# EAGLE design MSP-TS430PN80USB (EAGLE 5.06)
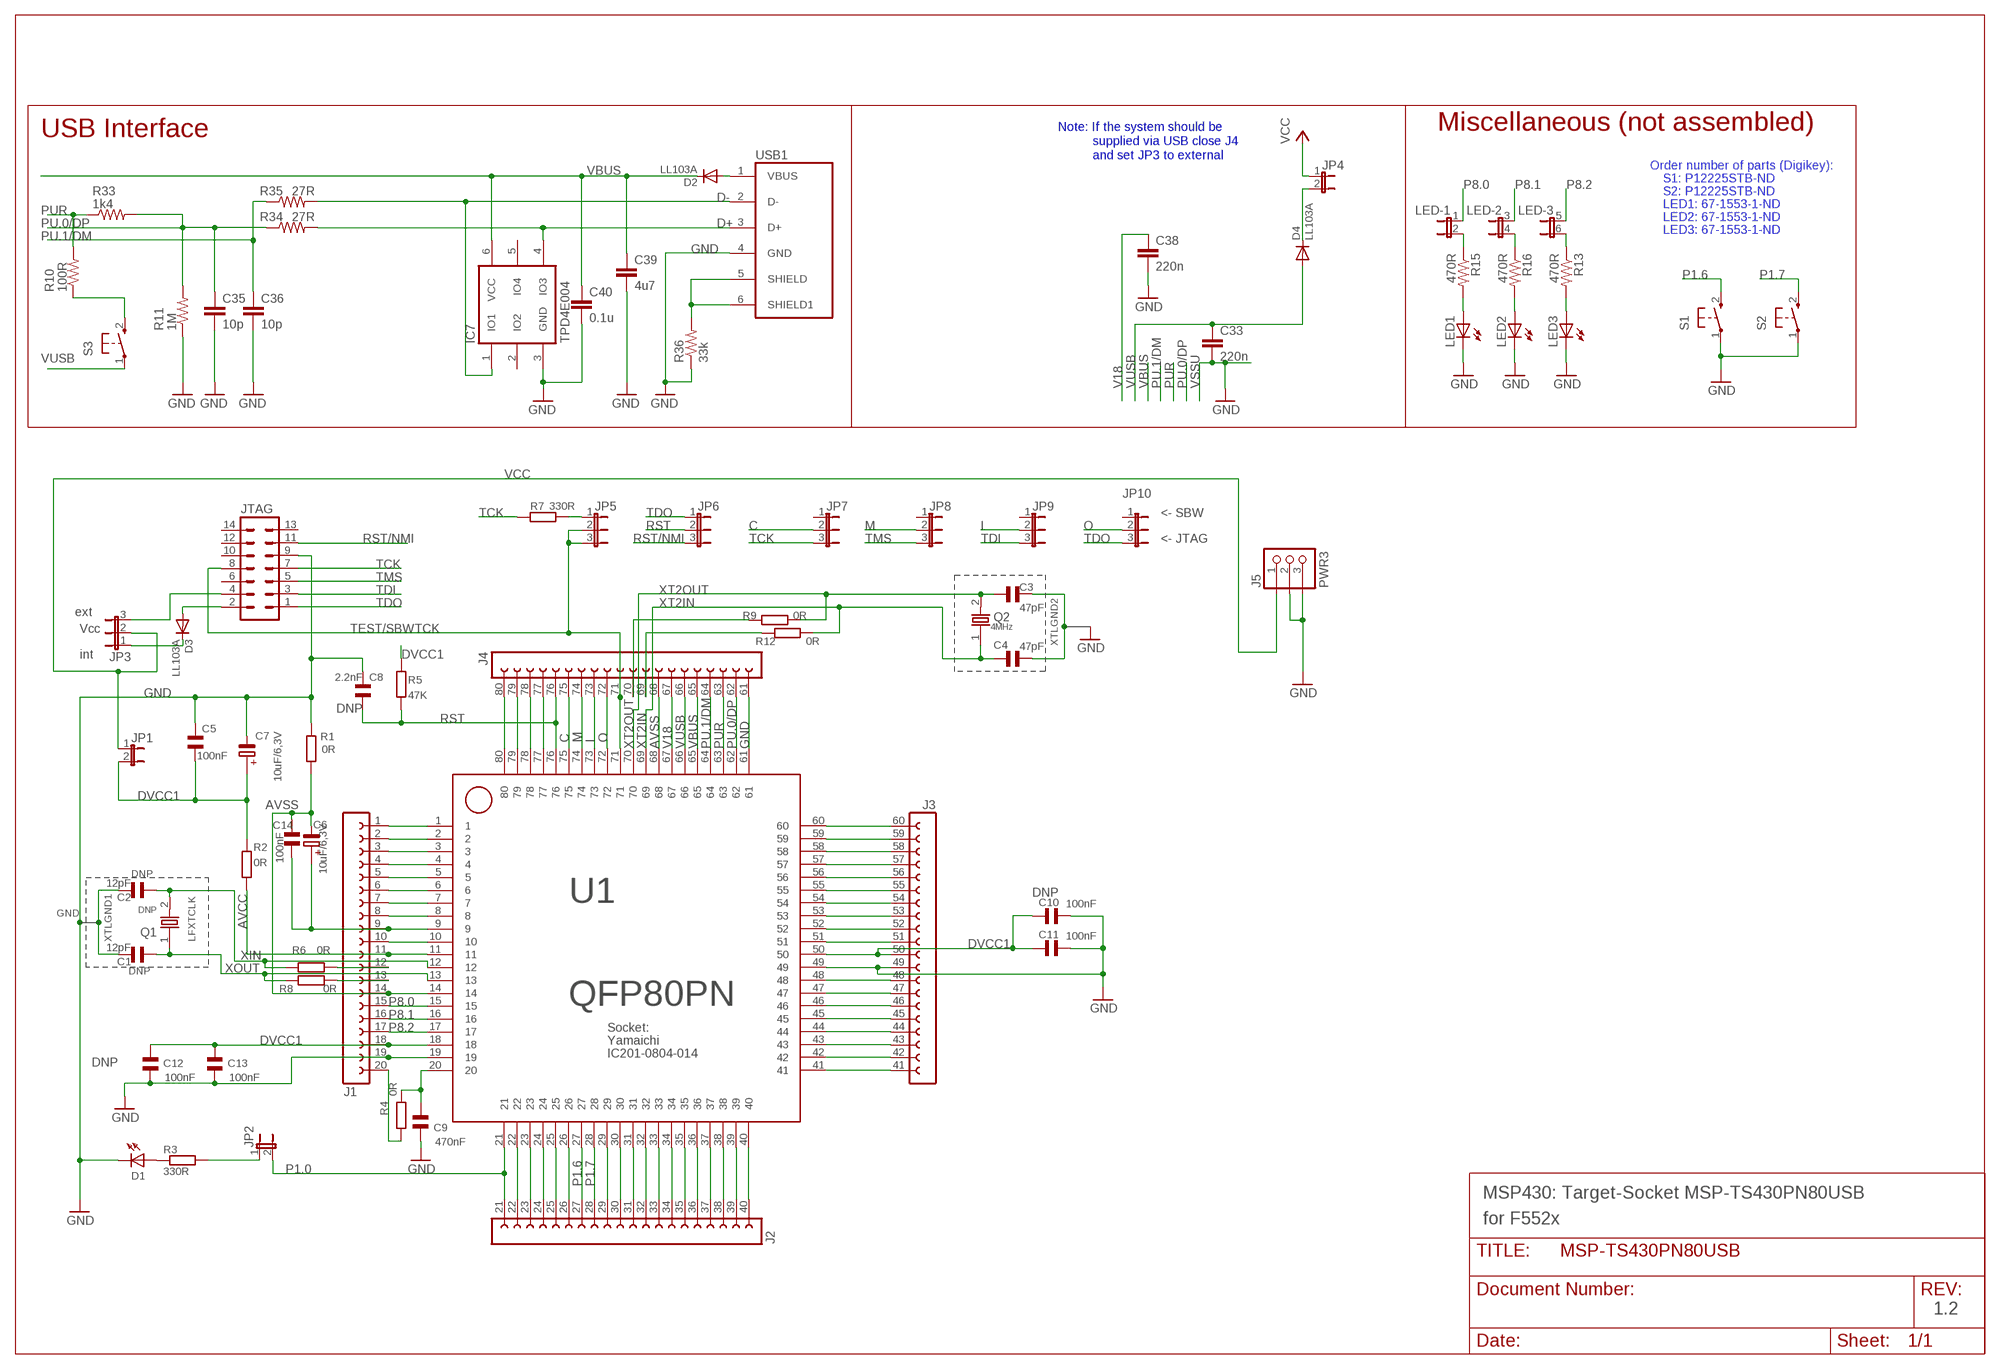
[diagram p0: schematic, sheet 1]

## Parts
C1  12pF  CSMD0805  [CSMD0805]
C2  12pF  CSMD0805  [CSMD0805]
C3  47pF  CSMD0805  [CSMD0805]
C4  47pF  CSMD0805  [CSMD0805]
C5  100nF  CSMD0805  [CSMD0805]
C6  10uF/6,3V  ELKO_1210  [1210ELKO]
C7  10uF/6,3V  ELKO_1210  [1210ELKO]
C8  2.2nF  CSMD0805  [CSMD0805]
C9  470nF  CSMD0805  [CSMD0805]
C10  100nF  CSMD0805  [CSMD0805]
C11  100nF  CSMD0805  [CSMD0805]
C12  100nF  CSMD0805  [CSMD0805]
C13  100nF  CSMD0805  [CSMD0805]
C14  100nF  CSMD0805  [CSMD0805]
C33  220n  C-EUC0603  [C0603]
C35  10p  C-EUC0603  [C0603]
C36  10p  C-EUC0603  [C0603]
C38  220n  C-EUC0603  [C0603]
C39  4u7  C-EUC0603  [C0603]
C40  0.1u  C-EUC0603  [C0603]
D1  LED30805  [DIODE_0805]
D2  LL103A  D  [SOD-80]
D3  LL103A  D  [SOD-80]
D4  LL103A  D  [SOD-80]
IC7  TPD4E004  [DRY6]
J1  FE20-1-1  [FE20-1-1]
J2  FE20-1-2  [FE20-1-2]
J3  FE20-1-3  [FE20-1-3]
J4  FE20-1-4  [FE20-1-4]
J5  PWR3  [PWR3]
JP1  JP1E  [JP1]
JP2  JP1E  [JP1]
JP3  JP2ESMALLPAD  [JP2Z]
JP4  JP1E  [JP1]
JP5  JP2ESMALLPAD  [JP2Z]
JP6  JP2ESMALLPAD  [JP2Z]
JP7  JP2ESMALLPAD  [JP2Z]
JP8  JP2ESMALLPAD  [JP2Z]
JP9  JP2ESMALLPAD  [JP2Z]
JP10  JP2ESMALLPAD  [JP2Z]
JTAG  ML14  [ML14]
LED  JP3QE  [JP3Q]
LED1  LEDCHIPLED_0603  [CHIPLED_0603]
LED2  LEDCHIPLED_0603  [CHIPLED_0603]
LED3  LEDCHIPLED_0603  [CHIPLED_0603]
Q1  HCTC_XTLTCV  [TCV]
Q2  HCTC_XTLTCV  [TCV]
R1  0R  R_0805  [0805]
R2  0R  R_0805  [0805]
R3  330R  R_0805  [0805]
R4  0R  R_0805  [0805]
R5  47K  R_0805  [0805]
R6  0R  R_0805  [0805]
R7  330R  R_0805  [0805]
R8  0R  R_0805  [0805]
R9  0R  R_0805  [0805]
R10  100R  R-US_R0603  [R0603]
R11  1M  R-US_R0603  [R0603]
R12  0R  R_0805  [0805]
R13  470R  R-US_R0603  [R0603]
R15  470R  R-US_R0603  [R0603]
R16  470R  R-US_R0603  [R0603]
R33  1k4  R-US_R0603  [R0603]
R34  27R  R-US_R0603  [R0603]
R35  27R  R-US_R0603  [R0603]
R36  33k  R-US_R0603  [R0603]
S1  PB  [PBTH]
S2  PB  [PBTH]
S3  PB  [PBTH]
U1  QFP80PN  [QFP80PN]
USB1  USB_RECEPTACLE  [USB_BUCHSE]

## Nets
AVCC: J1.11 R2.1 U1.11
AVSS: C6.- C14.2 J1.14 J4.68 R1.2 U1.14 U1.68
C: J4.75 JP7.2 U1.75
D+: IC7.4(IO3) R34.2 USB1.3(D+)
D-: IC7.1(IO1) R35.2 USB1.2(D-)
DVCC1: C5.1 C7.+ C10.1 C11.1 C12.2 C13.2 J1.18 J3.50 JP1.2 R2.2 R5.2 U1.18 U1.50
GND: C5.2 C7.- C8.1 C9.1 C10.2 C11.2 C12.1 C13.1 C33.2 C35.2 C36.2 C38.2 C39.2 C40.2 D1.K IC7.3(GND) J1.19 J3.49 J4.61 J5.2 J5.3 JTAG.9 LED1.C LED2.C LED3.C R1.1 R11.1 R36.1 S1.1(P) S2.1(P) U1.19 U1.49 U1.61 USB1.4(GND)
I: J4.73 JP9.2 U1.73
M: J4.74 JP8.2 U1.74
N$1: JP2.1 R3.2
N$2: D4.2(K) JP4.2
N$3: C6.+ C14.1 J1.9 U1.9
N$4: J1.20 R4.1
N$5: J4.70 R9.2
N$6: J1.12 R6.2
N$7: D3.2(K) JP3.1
N$8: R36.2 USB1.5(SHIELD) USB1.6(SHIELD1)
N$9: J1.1 U1.1
N$10: J1.13 R8.2
N$11: J4.69 R12.2
N$12: J1.2 U1.2
N$13: J1.3 U1.3
N$14: J2.30 U1.30
N$15: J1.4 U1.4
N$16: J2.39 U1.39
N$17: J4.80 U1.80
N$18: D1.A R3.1
N$19: J1.6 U1.6
N$20: J2.31 U1.31
N$21: J2.35 U1.35
N$22: J1.10 U1.10
N$23: JP3.3 JTAG.4
N$24: LED3.A R13.2
N$25: J3.47 U1.47
N$26: C9.2 R4.2 U1.20
N$27: J3.51 U1.51
N$28: J1.7 U1.7
N$29: J4.78 U1.78
N$30: LED.6 R13.1
N$31: R10.1 S3.2(S)
N$32: LED1.A R15.2
N$33: J3.48 U1.48
N$34: J2.32 U1.32
N$35: LED2.A R16.2
N$36: LED.2 R15.1
N$37: LED.4 R16.1
N$38: D3.1(A) JTAG.2
N$41: J2.22 U1.22
N$43: J2.23 U1.23
N$44: J2.24 U1.24
N$45: J2.25 U1.25
N$46: J2.26 U1.26
N$50: J2.29 U1.29
N$51: D2.1(A) USB1.1(VBUS)
N$54: J4.77 U1.77
N$55: J2.33 U1.33
N$56: J2.34 U1.34
N$57: JP5.1 R7.1
N$58: J2.36 U1.36
N$59: J2.37 U1.37
N$60: J2.38 U1.38
N$62: J2.40 U1.40
N$70: J3.41 U1.41
N$71: J3.42 U1.42
N$72: J3.43 U1.43
N$73: J3.44 U1.44
N$74: J3.45 U1.45
N$75: J3.46 U1.46
N$87: J3.52 U1.52
N$88: J3.53 U1.53
N$89: J3.54 U1.54
N$90: J3.55 U1.55
N$91: J3.56 U1.56
N$92: J3.57 U1.57
N$93: J3.58 U1.58
N$94: J3.59 U1.59
N$95: J3.60 U1.60
N$99: J1.8 U1.8
N$100: J4.79 U1.79
N$102: J1.5 U1.5
O: J4.72 JP10.2 U1.72
P1.0: J2.21 JP2.2 U1.21
P1.6: J2.27 S1.2(S) U1.27
P1.7: J2.28 S2.2(S) U1.28
P8.0: J1.15 LED.1 U1.15
P8.1: J1.16 LED.3 U1.16
P8.2: J1.17 LED.5 U1.17
PU.0/DP: C35.1 J4.62 R11.2 R33.2 R34.1 U1.62
PU.1/DM: C36.1 J4.64 R35.1 U1.64
PUR: J4.63 R10.2 R33.1 U1.63
RST: C8.2 J4.76 JP6.2 R5.1 U1.76
RST/NMI: JP6.3 JTAG.11
TCK: JP7.3 JTAG.7 R7.2
TDI: JP9.3 JTAG.3
TDO: JP6.1 JP10.3 JTAG.1
TEST/SBWTCK: J4.71 JP5.2 JP5.3 JTAG.8 U1.71
TMS: JP8.3 JTAG.5
V18: C38.1 J4.67 U1.67
VBUS: C39.1 C40.1 D2.2(K) IC7.6(VCC) J4.65 U1.65
VCC: J5.1 JP1.1 JP3.2 JP4.1
VUSB: C33.1 D4.1(A) J4.66 S3.1(P) U1.66
XIN: C2.1 Q1.2 R6.1 U1.12
XOUT: C1.1 Q1.1 R8.1 U1.13
XT2IN: C4.1 Q2.1 R12.1 U1.69
XT2OUT: C3.1 Q2.2 R9.1 U1.70
XTLGND1: C1.2 C2.2
XTLGND2: C3.2 C4.2
Unconnected: IC7.2(IO2) JP7.1 JP8.1 JP9.1 JP10.1 JTAG.6 JTAG.10 JTAG.12 JTAG.13 JTAG.14

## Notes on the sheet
- Note: If the system should be | Miscellaneous (not assembled)
- USB Interface
- supplied via USB close J4
- and set JP3 to external
- Order number of parts (Digikey):
- S1: P12225STB-ND
- S2: P12225STB-ND
- LED1: 67-1553-1-ND
- LED2: 67-1553-1-ND
- LED3: 67-1553-1-ND
- VSSU
- <- SBW
- <- JTAG
- ext
- 4MHz
- Vcc
- int
- DNP
- DNP
- DNP
- GND | DNP
- LFXTCLK
- DNP
- Socket:
- Yamaichi
- DNP | IC201-0804-014
- MSP430: Target-Socket MSP-TS430PN80USB
- for F552x
- 1.2

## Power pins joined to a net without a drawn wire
IO4: IC7.5(IO4)

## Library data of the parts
C1-C5 C8-C14 = cap:CSMD0805
C6 C7 = smd:ELKO_1210
C33 C35 C36 C38-C40 = rcl:C-EU: CAPACITOR, European symbol
D1 = MSP430:LED3
D2-D4 = smd:D
IC7 = gangprog:TPD4E004
J1 = CON-LSTA:FE20-1-1
J2 = CON-LSTA:FE20-1-2
J3 = CON-LSTA:FE20-1-3
J4 = CON-LSTA:FE20-1-4
J5 = MSP430:PWR3
JP1 JP2 JP4 = jumper:JP1E: JUMPER
JP3 JP5-JP10 = jumper:JP2E: JUMPER
JTAG = con-ml:ML14
LED = jumper:JP3QE: JUMPER
LED1-LED3 = led:LED: LED
Q1 Q2 = scrystal:HCTC_XTL
R1-R9 R12 = smd:R_0805
R10 R11 R33-R36 = rcl:R-US_: RESISTOR, American symbol
R13 R15 R16 = _MSP430:R-US_: RESISTOR, American symbol
S1-S3 = electricalmeter:PB: OMRON SWITCH
U1 = MSP430:QFP80PN
USB1 = susbfet:USB_RECEPTACLE: Lumberg: USB-Receptacle "B", 2413

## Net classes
0 default: width 0.254 mm

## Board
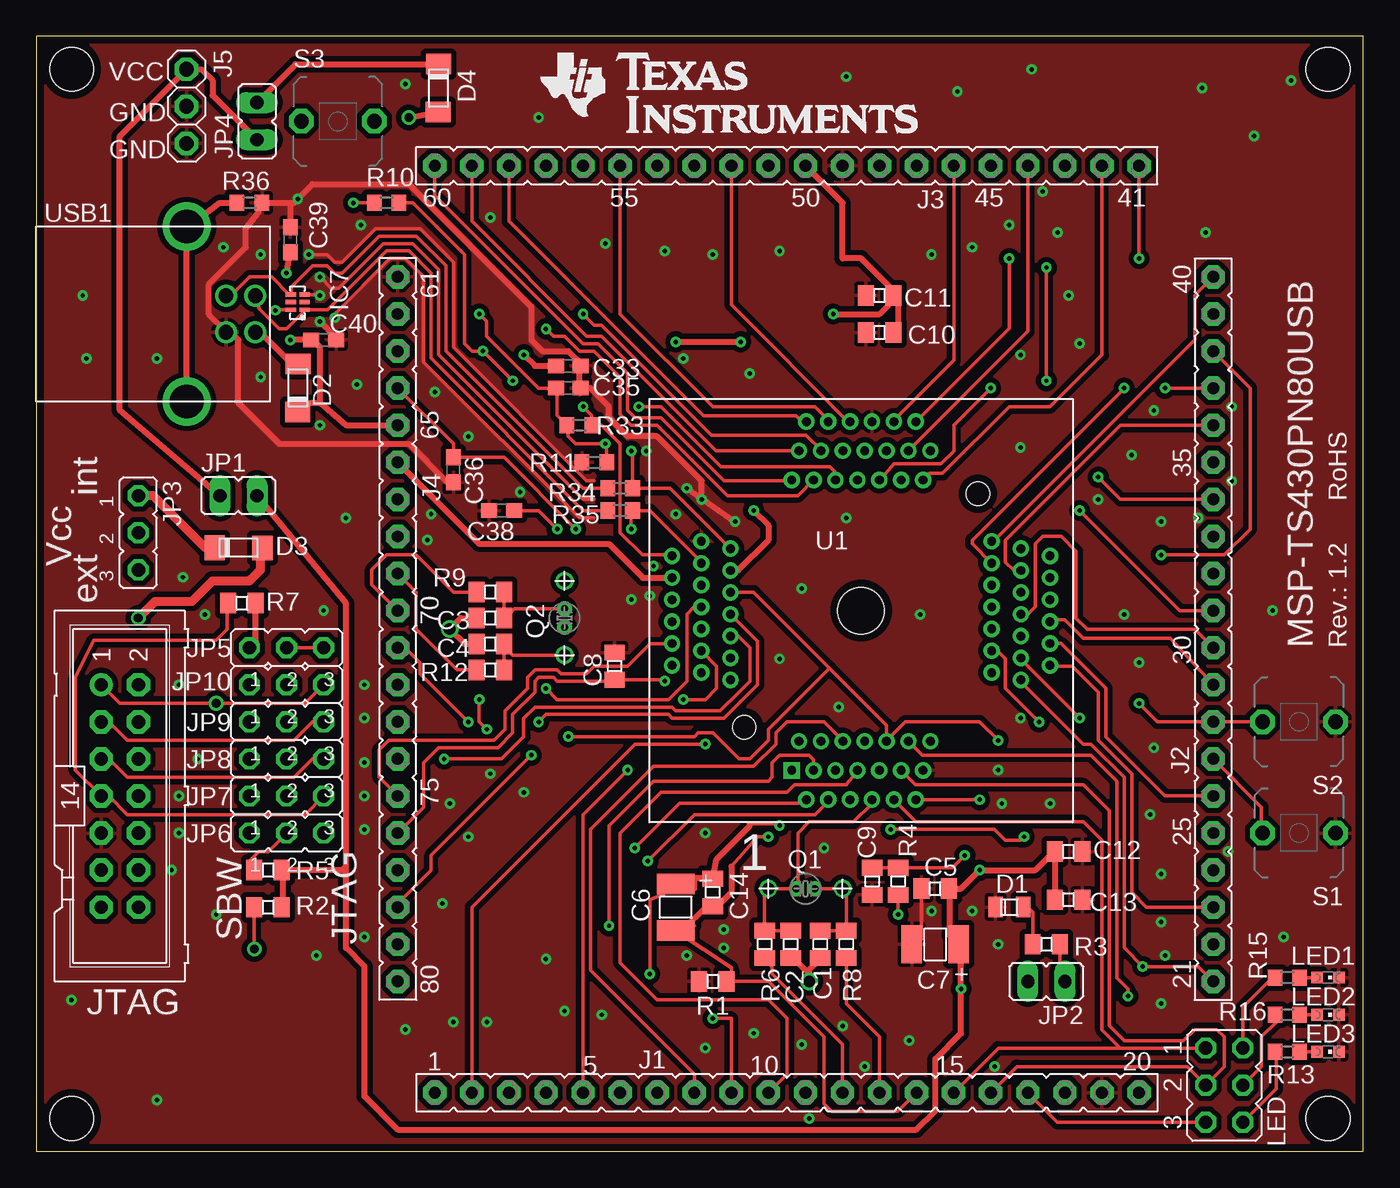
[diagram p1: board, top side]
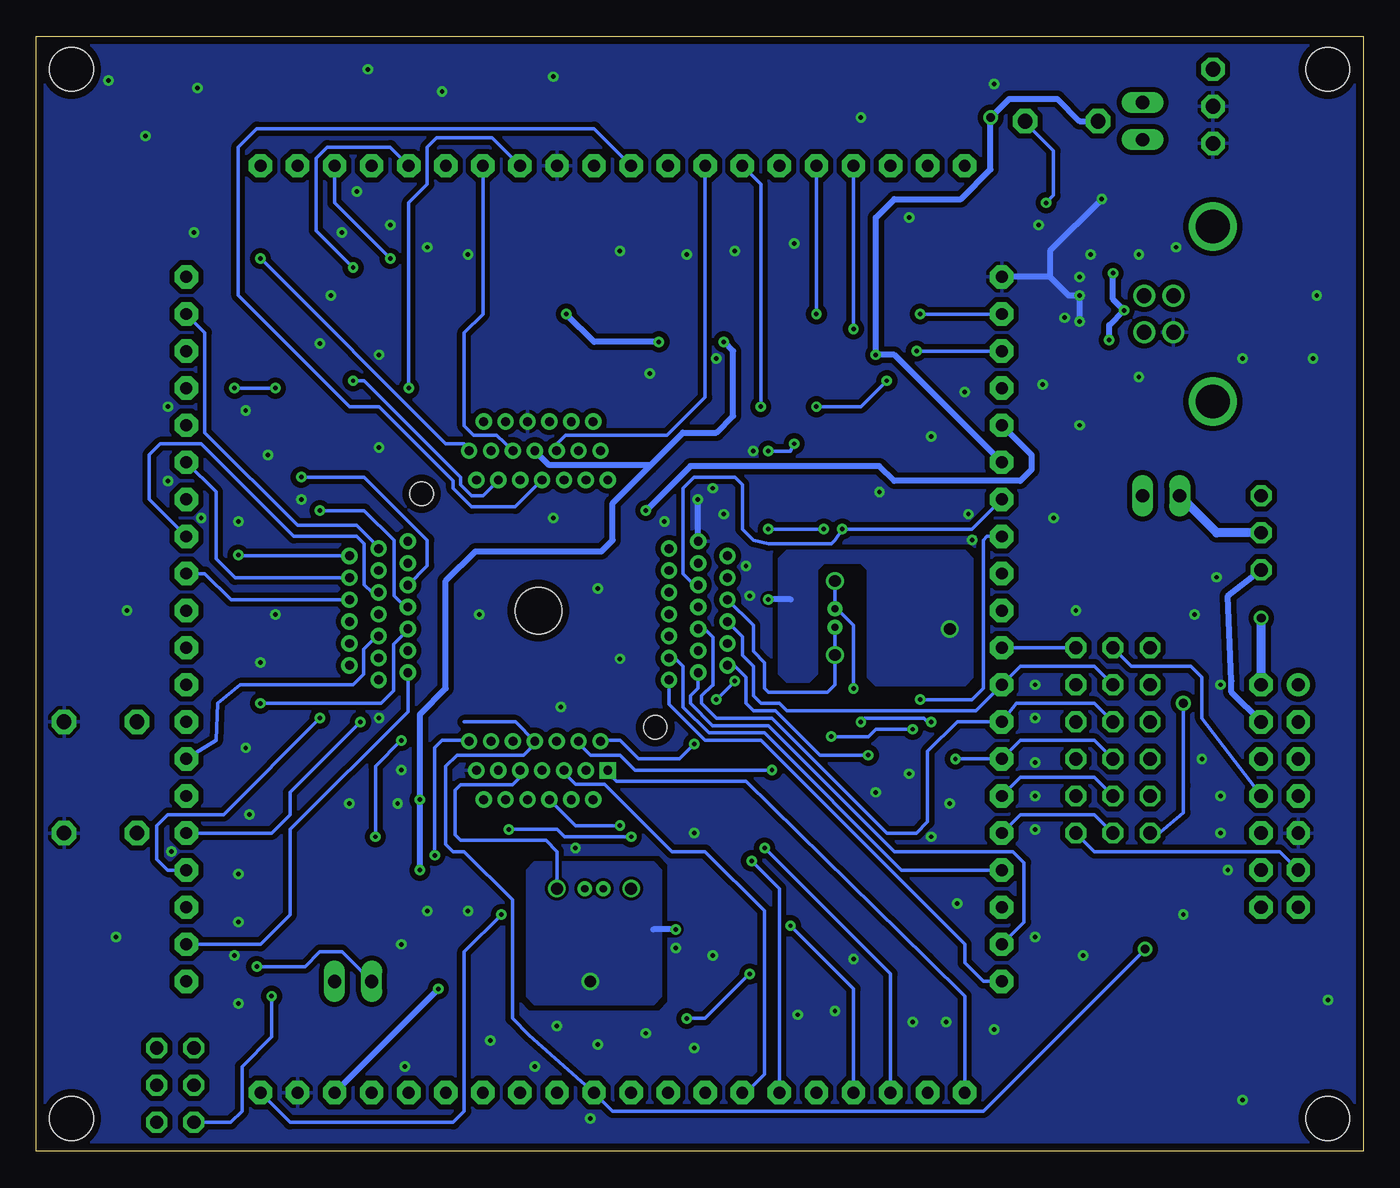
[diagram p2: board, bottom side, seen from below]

Size 90.91 x 76.38 mm. Coordinates in mm from the lower left corner, seen from the top.
Outline: 0,0 90.91,0 90.91,76.38 0,76.38 0,0
Copper layers (1*16): Top 0.035mm / dielectric 1.5mm / Bottom 0.035mm
Design rules "default *": minimum track width 8mil, minimum drill 12mil, track to track 8mil, track to pad 8mil, pad to pad 8mil, via to via 8mil, smd to smd 8mil, copper to edge 20mil, drill to drill 8mil, minimum pad ring 10mil, minimum via ring 8mil, stop-mask expansion 4mil, vias tented up to drill 0mil, thermal gap 10mil
Holes 3 mm at 2.41,74.13 88.51,74.13 88.51,2.25 2.41,2.25

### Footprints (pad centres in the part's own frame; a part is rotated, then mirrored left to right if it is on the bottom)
CSMD0805 = smd 1.092 x 1.397: 1 -0.94,0; 2 0.94,0
1210ELKO = smd 1.397 x 2.591: + 1.6,0; - -1.6,0
C0603 = smd 1.1 x 1: 1 -0.85,0; 2 0.85,0
DIODE_0805 = smd 1 x 1.4: A -0.94,0; K 0.94,0
SOD-80 = smd 1.397 x 1.702: 1 1.397,-0.025; 2 -1.88,0
DRY6 = smd 0.3 x 0.7: 1 -0.98,-2.254; 2 -0.457,-2.254; 3 0.066,-2.254; 4 0.066,-1.306; 5 -0.459,-1.306; 6 -0.98,-1.306
FE20-1-1 = drill 0.813 pad 1.6 octagon: 1 -24.13,0; 2 -21.59,0; 3 -19.05,0; 4 -16.51,0; 5 -13.97,0; 6 -11.43,0; 7 -8.89,0; 8 -6.35,0; 9 -3.81,0; 10 -1.27,0; 11 1.27,0; 12 3.81,0; 13 6.35,0; 14 8.89,0; 15 11.43,0; 16 13.97,0; 17 16.51,0; 18 19.05,0; 19 21.59,0; 20 24.13,0
FE20-1-2 = drill 0.813 pad 1.6 octagon: 21 -24.13,0; 22 -21.59,0; 23 -19.05,0; 24 -16.51,0; 25 -13.97,0; 26 -11.43,0; 27 -8.89,0; 28 -6.35,0; 29 -3.81,0; 30 -1.27,0; 31 1.27,0; 32 3.81,0; 33 6.35,0; 34 8.89,0; 35 11.43,0; 36 13.97,0; 37 16.51,0; 38 19.05,0; 39 21.59,0; 40 24.13,0
FE20-1-3 = drill 0.813 pad 1.6 octagon: 41 -24.13,0; 42 -21.59,0; 43 -19.05,0; 44 -16.51,0; 45 -13.97,0; 46 -11.43,0; 47 -8.89,0; 48 -6.35,0; 49 -3.81,0; 50 -1.27,0; 51 1.27,0; 52 3.81,0; 53 6.35,0; 54 8.89,0; 55 11.43,0; 56 13.97,0; 57 16.51,0; 58 19.05,0; 59 21.59,0; 60 24.13,0
FE20-1-4 = drill 0.813 pad 1.6 octagon: 61 -24.13,0; 62 -21.59,0; 63 -19.05,0; 64 -16.51,0; 65 -13.97,0; 66 -11.43,0; 67 -8.89,0; 68 -6.35,0; 69 -3.81,0; 70 -1.27,0; 71 1.27,0; 72 3.81,0; 73 6.35,0; 74 8.89,0; 75 11.43,0; 76 13.97,0; 77 16.51,0; 78 19.05,0; 79 21.59,0; 80 24.13,0
PWR3 = drill 1.016 pad 1.6 octagon: 1 -2.54,0; 2 0,0; 3 2.54,0
JP1 = drill 0.914 long: 1 0,-1.27; 2 0,1.27
JP2Z = drill 0.914 octagon: 1 -2.54,0; 2 0,0; 3 2.54,0
ML14 = drill 0.914 pad 1.6 round: 1 -7.62,-1.27 | drill 0.914 pad 1.6 octagon: 2 -7.62,1.27; 3 -5.08,-1.27; 4 -5.08,1.27; 5 -2.54,-1.27; 6 -2.54,1.27; 7 0,-1.27; 8 0,1.27; 9 2.54,-1.27; 10 2.54,1.27; 11 5.08,-1.27; 12 5.08,1.27; 13 7.62,-1.27; 14 7.62,1.27
JP3Q = drill 0.914 octagon: 1 -2.54,-1.27; 2 -2.54,1.27; 3 0,-1.27; 4 0,1.27; 5 2.54,-1.27; 6 2.54,1.27
CHIPLED_0603 = smd 0.8 x 0.8: A 0,-0.75; C 0,0.75
TCV = drill 0.5 round: 1 -0.635,0; 2 0.635,0
0805 = smd 1.092 x 1.397: 1 -0.94,0; 2 0.94,0
R0603 = smd 1 x 1.1: 1 -0.85,0; 2 0.85,0
PBTH = drill 1.016 pad 1.676 octagon: 1 -0.001,0.001; 2 5.001,0.001
QFP80PN = drill 0.61 pad 1 square: 1 -4.75,-10.95 | drill 0.61 pad 1 round: 2 -4.25,-8.95; 3 -3.75,-12.95; 4 -3.25,-10.95; 5 -2.75,-8.95; 6 -2.25,-12.95; 7 -1.75,-10.95; 8 -1.25,-8.95; 9 -0.75,-12.95; 10 -0.25,-10.95; 11 0.25,-8.95; 12 0.75,-12.95; 13 1.25,-10.95; 14 1.75,-8.95; 15 2.25,-12.95; 16 2.75,-10.95; 17 3.25,-8.95; 18 3.75,-12.95; 19 4.25,-10.95; 20 4.75,-8.95; 21 10.95,-4.75; 22 8.95,-4.25; 23 12.95,-3.75; 24 10.95,-3.25; 25 8.95,-2.75; 26 12.95,-2.25; 27 10.95,-1.75; 28 8.95,-1.25; 29 12.95,-0.75; 30 10.95,-0.25; 31 8.95,0.25; 32 12.95,0.75; 33 10.95,1.25; 34 8.95,1.75; 35 12.95,2.25; 36 10.95,2.75; 37 8.95,3.25; 38 12.95,3.75; 39 10.95,4.25; 40 8.95,4.75; 41 4.75,10.95; 42 4.25,8.95; 43 3.75,12.95; 44 3.25,10.95; 45 2.75,8.95; 46 2.25,12.95; 47 1.75,10.95; 48 1.25,8.95; 49 0.75,12.95; 50 0.25,10.95; 51 -0.25,8.95; 52 -0.75,12.95; 53 -1.25,10.95; 54 -1.75,8.95; 55 -2.25,12.95; 56 -2.75,10.95; 57 -3.25,8.95; 58 -3.75,12.95; 59 -4.25,10.95; 60 -4.75,8.95; 61 -10.95,4.75; 62 -8.95,4.25; 63 -12.95,3.75; 64 -10.95,3.25; 65 -8.95,2.75; 66 -12.95,2.25; 67 -10.95,1.75; 68 -8.95,1.25; 69 -12.95,0.75; 70 -10.95,0.25; 71 -8.95,-0.25; 72 -12.95,-0.75; 73 -10.95,-1.25; 74 -8.95,-1.75; 75 -12.95,-2.25; 76 -10.95,-2.75; 77 -8.95,-3.25; 78 -12.95,-3.75; 79 -10.95,-4.25; 80 -8.95,-4.75 | hole 3.2: 0,0 | hole 1.6: -8,-8; 8,8
USB_BUCHSE = drill 1 round: 1 1.25,7; 2 -1.25,7; 3 -1.25,5; 4 1.25,5 | drill 2.3 round: 5 -6,2.3; 6 6,2.3

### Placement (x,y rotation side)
C1  53.72,14.19 270 top
C2  51.68,14.19 270 top
C3  31.11,36.54 180 top
C4  31.11,34.76 180 top
C5  61.59,18 180 top
C6  43.81,16.73 90 top
C7  61.59,14.19 0 top
C8  39.62,33.24 270 top
C9  57.27,18.5 90 top
C10  57.78,56.1 180 top
C11  57.78,58.64 180 top
C12  70.73,20.54 180 top
C13  70.73,17.23 180 top
C14  46.35,17.74 270 top
C33  36.44,53.81 0 top
C35  36.44,52.29 0 top
C36  28.57,46.7 270 top
C38  31.87,43.9 180 top
C39  17.39,62.45 90 top
C40  19.68,55.59 0 top
D1  66.67,16.73 180 top
D2  17.9,52.54 90 top
D3  14.09,41.36 0 top
D4  27.55,72.61 270 top
IC7  16.12,58.64 90 top
J1  51.43,4.03 0 top
J2  80.64,35.78 90 top
J3  51.43,67.53 180 top
J4  24.76,35.78 270 top
J5  10.28,71.59 270 top
JP1  13.84,44.92 270 top
JP2  69.21,11.65 90 top
JP3  6.98,42.38 270 top
JP4  15.11,70.57 0 top
JP5  17.14,34.51 0 top
JP6  17.14,21.81 0 top
JP7  17.14,24.35 0 top
JP8  17.14,26.89 0 top
JP9  17.14,29.43 0 top
JP10  17.14,31.97 0 top
JTAG  5.71,24.35 270 top
LED  81.4,4.53 270 top
LED1  88.51,11.9 270 top
LED2  88.51,9.36 270 top
LED3  88.51,6.82 270 top
Q1  52.7,18 180 top
Q2  36.19,36.54 90 top
R1  46.35,11.65 0 top
R2  15.87,16.73 0 top
R3  69.21,14.19 0 top
R4  59.05,18.5 90 top
R5  15.87,19.27 0 top
R6  49.91,14.19 270 top
R7  14.09,37.55 180 top
R8  55.49,14.19 270 top
R9  31.11,38.32 180 top
R10  24,64.99 0 top
R11  38.22,47.21 0 top
R12  31.11,32.98 180 top
R13  85.72,6.82 0 top
R15  85.72,11.9 0 top
R16  85.72,9.36 0 top
R33  37.21,49.75 180 top
R34  40,45.43 180 top
R35  40,43.9 180 top
R36  14.6,64.99 180 top
S1  89.02,21.81 180 top
S2  89.02,29.43 180 top
S3  18.16,70.57 0 top
U1  56.51,37.05 0 top
U$1  [LOGO2008_TPLACE]  44.57,72.1 0 top
USB1  8,57.37 270 top

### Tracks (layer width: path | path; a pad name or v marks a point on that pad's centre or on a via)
AVCC  (via drill 0.6)
  Top 0.254: v14.93,13.86 R2.1
  Bottom 0.254: 61.59,29.43 58.09,29.43 U1.11 56.76,27.91 57.53,27.14 62.1,27.14 62.86,26.38 62.86,21.04 62.35,20.54 61.59,20.54 58.29,17.23 58.29,9.11 57.15,7.96 J1.11 51.43,2.76 26.03,2.76 v14.93,13.86
AVSS  (via drill 0.3)
  Top 0.254: 47.62,11.65 50.16,11.65 53.97,7.84 53.97,3.26 54.48,2.76 59.05,2.76 J1.14 | 47.62,11.65 R1.2 | 47.62,11.65 47.62,12.59 C6.- 45.08,15.46 | 58.29,28.12 U1.14 58.26,28.13 | 58.26,28.13 59.56,29.43 64.64,29.43 v65.91,28.16 | 47.62,19.52 49.4,21.55 v50.16,21.55 | v67.69,21.55 67.43,21.3 66.42,21.3 65.65,22.06 v58.54,22.06 | 58.26,28.13 58.26,29.2 54.35,33.11 | 54.35,33.11 49.14,38.32 47.62,38.32 47.6,38.3 U1.68 | v30.35,30.95 30.35,29.43 v30.86,28.92 | v36.44,28.41 45.08,28.41 45.33,28.66 46.35,28.66 48.13,26.89 48.89,26.89 50.16,28.16 50.16,28.92 54.35,33.11
  Top 0.406: 47.62,19.52 47.62,17.74 46.6,16.73 C14.2 45.92,16.8 44.32,15.2 C6.-
  Bottom 0.254: v65.91,28.16 67.69,26.38 v67.69,21.55 | v50.16,21.55 54.73,21.55 55.24,22.06 v58.54,22.06 | J4.68 25.78,42.13 26.03,41.87 26.03,31.71 26.79,30.95 v30.35,30.95 | v30.86,28.92 33.4,28.92 33.9,28.41 v36.44,28.41
C
  Top 0.254: U1.75 43.56,34.76 42.03,34.76 40.51,33.24 38.22,33.24 37.71,32.73 35.94,32.73 35.68,32.98 34.16,32.98 33.65,32.47 33.65,31.71 32.13,30.19 32.13,28.92 31.36,28.16 24.12,28.16 23.49,27.52 23.49,25.62 J4.75
  Bottom 0.254: JP7.2 18.41,25.62 23.49,25.62 J4.75
D+
  Top 0.254: USB1.3 13.31,58.62 14.6,59.91 16.12,59.91 17.33,58.7 IC7.4 17.46,58.7 17.46,59.21 18.92,60.67 19.93,60.67 20.44,60.16 20.95,60.16 23.49,62.7 26.03,62.7 28.06,60.67 28.06,54.83 37.46,45.43 R34.2 39.24,45.43
D-
  Top 0.254: USB1.2 15.25,57.73 16.63,56.35 17.14,56.35 18.41,57.62 IC7.1 19.97,57.66 24,61.68 25.52,61.68 27.05,60.16 27.05,54.32 37.46,43.9 R35.2 39.24,43.9
DVCC1  (via drill 0.3, 0.3 pad 0.61)
  Top 0.254: 59.05,56.1 C10.1 | 59.05,58.31 C11.1 59.05,58.64 | 69.79,20.21 69.72,20.54 C12.2 | 62.61,18 62.86,18 | U1.18 v64.64,24.09
  Top 0.406: 59.05,58.31 59.05,56.1 | v43.81,55.46 v48.26,55.46 | v54.61,57.37 57.78,57.37 59.05,58.64 56.51,61.18 55.24,61.18 55.24,64.99 J3.50 | C13.2 69.79,20.21 C12.2 | C5.1 62.61,18 62.61,14.77 C7.+ 63.37,14.19 v63.37,11.14 63.37,8.09 61.59,6.31 61.59,2.76 60.32,1.49 24.76,1.49 22.47,3.77 22.47,12.66 21.2,13.93 21.2,19.52 | 62.86,18 63.37,18 v64.64,19.27 68.45,19.27 69.72,20.54 | JP1.2 21.2,37.55 21.2,19.52 | 21.2,19.52 20.95,19.27 R5.2 16.89,19.19 16.89,16.73 R2.2
  Bottom 0.406: v43.81,55.46 43.17,54.83 43.17,50.38 44.32,49.24 46.6,49.24 48.89,46.95 | v48.26,55.46 52.7,55.46 v54.61,57.37 | v64.64,19.27 v64.64,24.09 64.64,29.93 62.86,31.71 62.86,39.08 60.83,41.11 52.19,41.11 51.43,41.87 51.43,44.41 48.89,46.95 | U1.50 55.78,47.02 48.95,47.02 48.89,46.95 | v63.37,11.14 J1.18
GND  (via drill 0.3, 0.3 pad 0.3)
  Top 0.254: C7.- 60.32,14.19 60.65,14.52 C5.2 | v19.43,59.91 20.19,59.14 20.7,59.14 23.74,62.19 25.78,62.19 27.55,60.41 27.55,54.57 37.46,44.67 38.22,44.67 | v18.66,61.43 19.93,61.43 20.44,60.92 20.95,60.92 23.24,63.21 26.28,63.21 28.57,60.92 28.57,55.08 37.71,45.94 38.22,45.94 | v20.44,57.11 20.44,57.37 24.25,61.18 25.27,61.18 26.54,59.91 26.54,54.06 37.21,43.4 38.22,43.4 | IC7.3 19.36,58.7 v19.43,58.64
  Top 0.406: v44.57,45.43 v47.87,43.14 | 17.31,63.3 C39.2 17.39,64.99 | C40.2 20.53,55.75 v19.43,56.86 | C36.2 28.15,45.85 25.52,48.48 16.63,48.48 13.84,51.27 13.84,55.59 13.31,56.12 USB1.4 13.06,56.12 11.81,57.37 11.81,59.4 14.35,61.94 14.35,63.21 15.2,64.31 15.36,64.91 15.36,64.73 R36.1 17.39,64.99 | 37.46,53.81 36.44,54.83 34.67,54.83 33.9,55.59 33.9,57.87 25.52,66.26 18.92,66.26 v17.9,65.24 17.65,64.99 17.39,64.99 | C35.2 37.21,52.29 | C35.2 37.97,52.29 39.24,51.02 39.24,50.25 40.51,48.98 42.54,48.98 45.59,45.94 v45.59,44.67 | C35.2 37.21,52.37 37.21,53.81
  Bottom 0.406: 21.46,59.91 20.19,58.64 v19.43,58.64 v19.43,56.86 | 21.46,59.91 J4.61 | 21.46,59.91 21.46,61.68 v17.9,65.24 | U1.61 45.56,41.84 45.59,41.87 v45.59,44.67
  other vias: 40.76,37.81 47.11,15.2 25.27,73.11 85.97,73.37 83.43,69.56 79.88,72.86 68.19,74.13 63.11,72.61 55.49,73.62 34.41,70.83 50.92,61.68 46.35,61.43 43.05,61.68 60.57,36.79 67.43,48.22 55.49,43.4 48.89,53.3 8.25,3.52 2.41,10.38 12.31,16.22 9.27,19.27 9.77,24.35 11.04,26.89 9.77,31.97 10.03,39.33 19.68,37.05 21.2,43.4 19.43,49.75 21.97,52.54 8.25,54.32 3.42,54.32 3.17,58.64 33.4,24.6 28.32,23.84 38.98,62.19 29.59,48.98 28.57,8.85 27.81,16.98 30.86,8.85 38.73,9.36 45.84,7.07 59.81,7.58 77.08,19.01 75.56,33.49 75.05,47.71 34.92,13.17 49.14,8.09 52.45,7.33 55.24,8.6 45.84,21.81 77.08,15.71 76.32,23.08 76.58,27.65 85.47,14.69 84.7,37.05 77.08,43.14 70.73,58.64 61.34,61.43 66.67,63.46 81.91,45.94 79.62,43.4 27.3,52.03 31.11,63.97 44.32,54.32 22.47,31.97 22.47,29.68 22.47,26.63 22.47,24.35 43.81,43.65 67.43,29.68 81.66,20.54 27.05,43.65 26.79,41.87 31.11,25.87 36.19,9.61 47.11,13.93 44.57,13.42 56.76,5.8 64.13,16.47 61.34,16.47 69.46,23.84 65.91,26.12 64.13,61.94 67.43,54.57 71.5,55.33 69.97,62.95 68.96,65.75 76.58,50.76 74.54,36.79 72.77,44.67 66.16,23.84 29.59,21.55 25.27,8.34 19.17,13.42 22.47,14.69 22.47,22.06 33.14,45.17 12.82,61.94 15.36,61.43 15.36,53.05 22.22,63.46 50.92,33.74 54.99,30.44 53.97,20.79 52.95,2.25 65.65,5.8 42.03,38.06 42.29,40.09 52.45,38.57 77.08,10.12 65.91,14.19 80.13,62.95 81.91,51.02 77.34,13.42 41.78,47.97 9.77,21.81 11.55,36.79
  pour Bottom (isolate 0.356, rank 2): 0.12,76.42 90.8,76.42 90.8,-0.04 0.12,-0.04
  pour Top (isolate 0.356, rank 2): 0.12,76.42 90.8,76.42 90.8,-0.04 0.12,-0.04
I
  Bottom 0.254: U1.73 45.12,35.8 44.55,35.22 44.55,31.94 44.6,31.94 45.33,31.2 45.33,30.7 44.32,29.68 40.51,29.68 32.63,21.81 30.6,21.81 29.84,22.57 29.84,27.39 27.81,29.43 J4.73 23.74,30.7 18.41,30.7 JP9.2
M  (via drill 0.3)
  Top 0.254: U1.74 48.1,35.3 48.89,34.51 48.89,32.22 48.13,31.46 | 48.13,31.46 48.07,31.39 | v27.94,26.89 31.87,26.89 33.4,28.41 33.4,29.68 34.16,30.44 43.56,30.44 43.81,30.19 46.86,30.19 48.13,31.46
  Bottom 0.254: v27.94,26.89 J4.74 23.49,28.16 18.41,28.16 JP8.2
N$1
  Top 0.254: R3.2 70.15,11.98 JP2.1
N$2
  Top 0.406: D4.2 17.75,74.49 JP4.2
N$3  (via drill 0.3, 0.3 pad 0.61)
  Top 0.254: v46.35,9.11 47.62,9.11 J1.9 | v42.03,12.15 42.03,17.23 43.81,18 45.08,18 C6.+ | 48.89,22.44 50.8,22.44 v50.92,22.31
  Top 0.406: 45.08,18 45.08,18.76 46.6,18.76 C14.1 46.6,20.03 48.89,22.31 48.89,22.44
  Bottom 0.254: v46.35,9.11 45.08,9.11 v42.03,12.15 | U1.9 53.97,22.31 v50.92,22.31
N$4  (via drill 0.3 pad 0.3)
  Top 0.254: v59.05,16.22 R4.1
  Bottom 0.254: J1.20 73.53,1.99 62.35,1.99 61.59,2.76 61.59,13.68 v59.05,16.22
N$5
  Top 0.254: J4.70 22.98,38.82 22.98,39.84 24,40.86 26.03,40.86 28.57,38.32 R9.2
N$6
  Top 0.254: J1.12 55.24,7.33 50.41,12.15 50.41,12.66 49.91,13.17 R6.2
N$7
  Top 0.406: D3.2 11.55,41.36
  Top 0.61: 11.55,41.36 8,44.92 JP3.1
N$8
  Top 0.406: USB1.6 10.3,63.19 10.54,63.21 10.55,63.22 USB1.5 10.55,63.45 10.54,63.46 12.57,64.99 R36.2
N$9
  Bottom 0.254: J1.1 27.3,10.63 29.84,13.17 42.29,25.36 51.18,25.36 51.91,26.1 | 51.91,26.1 51.94,26.12 | 51.91,26.1 U1.1
N$10
  Top 0.254: J1.13 57.78,7.84 55.49,10.12 R8.2
N$11
  Top 0.254: R12.2 28.82,32.98 26.03,35.78 26.03,38.32 J4.69
N$12  (via drill 0.3)
  Top 0.254: v45.84,27.9 41.02,27.9 29.84,16.73 J1.2
  Bottom 0.254: v45.84,27.9 46.86,26.89 49.65,26.89 50.92,28.16 52.2,28.16 U1.2
N$13  (via drill 0.3)
  Top 0.254: U1.3 52.5,23.84 44.06,23.84 v41.02,20.79
  Bottom 0.254: v41.02,20.79 32.38,12.15 J1.3
N$14
  Top 0.254: U1.30 67.94,36.8 68.45,37.3 68.45,41.62 68.96,42.13 70.23,42.13 71.24,41.11 71.24,36.54 72,35.78 79.37,35.78 J2.30
N$15  (via drill 0.3)
  Top 0.254: U1.4 53.26,26.83 52.95,27.14 50.92,27.14 50.41,26.63 50.41,25.62 50.16,25.36 42.29,25.36 39.24,22.31 v39.24,15.46
  Bottom 0.254: v39.24,15.46 34.92,11.14 J1.4
N$16
  Bottom 0.254: U1.39 67.46,41.39 68.96,42.89 73.02,42.89 79.37,49.24 79.37,56.1 J2.39
N$17
  Bottom 0.254: J4.80 26.03,11.65 27.3,12.92 27.3,14.19 41.27,28.16 45.08,28.16 47.56,30.64 U1.80
N$18
  Top 0.254: D1.A 67.94,16.73 68.27,16.4 R3.1
N$19  (via drill 0.3 pad 0.61)
  Top 0.254: U1.6 54.26,24 53.34,23.08 46.35,23.08 | 46.35,23.08 45.72,23.08 | v41.91,19.9 45.08,23.08 46.35,23.08
  Bottom 0.254: v41.91,19.9 40,18 J1.6
N$20  (via drill 0.3)
  Top 0.254: v71.5,43.9 78.35,37.05 J2.31
  Bottom 0.254: U1.31 65.65,37.3 66.42,38.06 66.42,41.87 68.45,43.9 v71.5,43.9
N$21
  Bottom 0.254: U1.35 77.3,39.3 78.61,40.6 78.61,45.17 J2.35
N$22
  Top 0.254: 56.1,25.84 56.26,26 | 56.1,25.84 U1.10 | 56.1,25.84 55.52,25.16 55.49,25.13 55.49,25.11 51.94,25.11 51.43,24.6 44.32,24.6 | 44.32,24.6 44.27,24.6 | 44.32,24.6 42.79,24.6 40,21.81 40,12.92 42.54,10.38 50.16,10.38 51.43,9.11 51.43,5.3 J1.10
N$23
  Bottom 0.406: JTAG.4 9.01,31.46 9.01,32.22 9.27,38.06 JP3.3
N$24
  Top 0.254: R13.2 LED3.A
N$25
  Bottom 0.254: U1.47 59.38,49.06 60.96,49.06 61.59,49.7 61.59,56.1 60.32,57.37 J3.47
N$26  (via drill 0.3 pad 0.3)
  Top 0.254: C9.2 57.27,19.52 57.35,19.44 R4.2 62.78,19.44 v63.62,20.28
  Bottom 0.254: v63.62,20.28 63.62,27.65 63.11,28.16 61.34,28.16 61.28,28.1 U1.20
N$27
  Bottom 0.254: U1.51 58.1,44.16 61.08,44.16 62.35,45.43 62.35,45.94 67.43,51.02 69.46,51.02 77.08,58.64 77.08,68.8 75.81,70.07 52.7,70.07 J3.51
N$28
  Bottom 0.254: 54.76,25.77 U1.7 54.76,25.95 53.97,25.16 51.99,25.16 47.37,20.54 45.59,20.54 | 45.59,20.54 45.08,20.54 41.02,16.47 41.02,5.3 42.29,4.03 J1.7 | 45.59,20.54 45.72,20.54
N$29  (via drill 0.3)
  Top 0.254: J4.78 24.76,16.98 27.05,19.27 27.05,20.28 v33.9,27.14
  Bottom 0.254: U1.78 43.11,33.3 42.29,32.47 42.29,30.7 41.78,30.19 40.25,30.19 37.21,27.14 v33.9,27.14
N$30
  Top 0.254: R13.1 84.96,6.82 84.96,4.28 LED.6
N$31  (via drill 0.3 pad 0.3)
  Top 0.254: v21.71,64.99 R10.1
  Bottom 0.254: v21.71,64.99 21.2,65.49 21.2,68.54 23.24,70.57 23.23,70.58 S3.2
N$32
  Top 0.254: R15.2 LED1.A
N$33  (via drill 0.3 pad 0.61)
  Top 0.254: U1.48 57.78,45.98 57.78,45.94 58.77,47.1 62,47.1 62.86,47.97 62.86,49.75 v65.4,52.29
  Bottom 0.254: v65.4,52.29 65.4,64.99 64.13,66.26 64.13,68.8 63.5,69.43 59.69,69.43 J3.48
N$34
  Bottom 0.254: U1.32 77.58,37.8 79.37,39.59 J2.32
N$35
  Top 0.254: R16.2 LED2.A
N$36
  Top 0.254: R15.1 84.7,11.9 82.67,9.87 LED.2
N$37
  Top 0.254: LED.4 83.94,5.8 83.94,7.84 84.96,8.85 84.96,9.36 R16.1
N$38  (via drill 0.6)
  Top 0.61: v6.98,36.54 8.12,37.68 10.66,37.68 12.06,39.08 14.6,39.08 15.36,39.84 15.36,41.21 D3.1
  Bottom 0.61: JTAG.2 v6.98,36.54
N$41
  Bottom 0.254: U1.22 65.46,30.13 73.53,22.06 73.53,16.22 75.56,14.19 J2.22
N$43
  Top 0.254: J2.23 76.07,16.73 75.05,17.74 75.05,25.87 72.77,28.16 72.77,31.46 70.99,33.24 69.46,33.24 U1.23
N$44  (via drill 0.3)
  Top 0.254: U1.24 67.46,33.72 v71.5,29.68
  Bottom 0.254: v71.5,29.68 78.1,23.08 81.91,23.08 82.67,22.31 82.67,20.03 81.91,19.27 J2.24
N$45  (via drill 0.3)
  Top 0.254: U1.25 65.86,34.3 66.42,33.74 66.42,31.71 v68.7,29.43
  Bottom 0.254: v68.7,29.43 73.53,24.6 73.53,23.08 74.8,21.81 J2.25
N$46
  Top 0.254: U1.26 70.19,34.8 73.27,31.71 73.27,28.41 77.34,24.35 J2.26
N$50
  Top 0.254: J2.29 77.72,35.14 71.75,35.14 70.48,36.41 69.58,36.41 U1.29
N$51
  Top 0.406: USB1.1 15.34,56.12 17.52,53.94 D2.1
N$54
  Bottom 0.254: U1.77 47.16,33.8 46.6,33.24 46.6,30.44 44.83,28.66 41.02,28.66 31.62,19.27 J4.77
N$55
  Bottom 0.254: U1.33 67.92,38.3 68.45,38.82 68.45,41.62 68.96,42.13 73.27,42.13 79.62,48.48 82.42,48.48 83.18,47.71 83.18,44.67 J2.33
N$56  (via drill 0.3)
  Top 0.254: v72.77,46.19 74.29,44.67 J2.34
  Bottom 0.254: U1.34 64.13,40.13 64.13,41.87 68.45,46.19 v72.77,46.19
N$57
  Top 0.406: R7.1 15.03,34.94 JP5.1
N$58
  Top 0.254: U1.36 66.97,39.8 66.42,40.35 66.42,41.87 74.29,49.75 J2.36
N$59  (via drill 0.3)
  Top 0.254: U1.37 64.13,41.62 64.13,41.87 v74.54,52.29 | v77.34,52.29 J2.37
  Bottom 0.254: v74.54,52.29 v77.34,52.29
N$60  (via drill 0.3)
  Top 0.254: v77.08,40.86 81.4,40.86 83.18,42.63 83.18,52.29 J2.38
  Bottom 0.254: U1.38 77.02,40.8 v77.08,40.86
N$62
  Top 0.254: U1.40 65.58,41.8 79.37,55.59 79.37,58.64 J2.40
N$70  (via drill 0.3 pad 0.61)
  Top 0.254: v75.56,61.18 J3.41
  Bottom 0.254: v75.56,61.18 62.86,48.48 61.59,48.48 61.59,48.37 61.26,48.04 U1.41
N$71
  Top 0.254: J3.42 73.02,54.57 69.46,51.02 66.67,51.02 62.1,46.44 61.21,46.44 U1.42
N$72  (via drill 0.3 pad 0.61)
  Top 0.254: U1.43 66.67,56.41 v66.67,61.18
  Bottom 0.254: v66.67,61.18 70.48,64.99 J3.43
N$73
  Top 0.254: U1.44 67.94,56.18 J3.44
N$74  (via drill 0.3, 0.3 pad 0.61)
  Top 0.254: v69.21,52.79 v69.21,60.54
  Bottom 0.254: J3.45 66.67,68.8 70.99,68.8 71.75,68.03 71.75,63.08 v69.21,60.54 | U1.45 59.26,45.98 60.32,44.92 61.08,44.92 61.84,45.68 61.84,46.19 68.45,52.79 v69.21,52.79
N$75
  Top 0.254: U1.46 58.76,50.09 62.86,54.19 J3.46
N$87
  Top 0.254: J3.52 47.62,58 55.76,49.86 55.76,50.27 | U1.52 55.76,50.27 | 55.76,50.27 55.88,50.38
N$88
  Bottom 0.254: U1.53 55.26,48.46 54.66,49.06 47.7,49.06 45.08,51.65 J3.53
N$89  (via drill 0.3 pad 0.61)
  Top 0.254: U1.54 54.76,46.52 54.38,46.9 46.91,46.9 42.79,51.02 v41.27,51.02
  Bottom 0.254: v41.27,51.02 41.27,66.26 J3.54
N$90
  Top 0.254: J3.55 40,57.37 46.35,51.02 53.34,51.02 54.26,50.09 U1.55
N$91  (via drill 0.3 pad 0.61)
  Top 0.254: 53.82,48 53.97,47.84 | 53.82,48 U1.56 | 53.82,48 52.75,49.06 46.27,49.06 38.73,56.6 38.22,56.6 v37.46,57.37
  Bottom 0.254: v37.46,57.37 J3.56
N$92  (via drill 0.3 pad 0.3)
  Top 0.254: U1.57 52.19,44.93 52.19,44.92 47.37,44.92 42.54,49.75 40.76,49.75 40,50.51 40,53.05 38.22,54.83 37.21,54.83 36.19,55.84 35.43,55.84 v34.92,56.35
  Bottom 0.254: v34.92,56.35 J3.57
N$93
  Top 0.254: J3.58 32.38,63.72 45.72,50.38 52.07,50.38 52.7,49.75 52.76,49.81 U1.58
N$94
  Top 0.254: J3.59 29.84,63.72 37.71,55.84 38.73,55.84 46.58,48 U1.59
N$95
  Top 0.254: U1.60 51.49,46 51.43,45.94 47.11,45.94 42.79,50.25 41.02,50.25 40.51,50.76 40.51,53.3 38.48,55.33 37.46,55.33 27.3,65.49 J3.60
N$99
  Top 0.254: U1.8 55.26,28.14 53.97,29.43 51.43,29.43 50.67,28.66 50.67,27.9 49.14,26.38 42.29,26.38 37.97,22.06 37.97,12.41 45.08,5.3 J1.8
N$100
  Bottom 0.254: U1.79 45.56,31.74 46.1,31.2 46.1,30.7 44.57,29.17 40.76,29.17 32.13,20.54 24,20.54 23.24,19.77 23.24,15.71 J4.79
N$102  (via drill 0.3 pad 0.61)
  Top 0.254: v40.51,26.12 37.46,23.08 J1.5
  Bottom 0.254: 53.91,28.1 53.97,28.16 | 53.91,28.1 U1.5 | 53.91,28.1 52.95,27.14 50.92,27.14 49.91,26.12 v40.51,26.12
O
  Bottom 0.254: JP10.2 18.41,33.24 23.49,33.24 J4.72 26.54,30.19 39.49,30.19 40,30.7 41.27,30.7 41.78,31.2 41.78,33.24 42.54,34 42.54,35.27 U1.72
P1.0  (via drill 0.3)
  Top 0.254: J2.21 79.62,12.66 v75.81,12.66 74.54,13.93 74.54,25.62 72.26,27.9 71.75,27.9 67.43,32.22 67.46,32.25 U1.21
  Bottom 0.254: v75.81,12.66 72.51,12.66 71.5,13.68 69.97,13.68 JP2.2
P1.6
  Top 0.254: S1.2 83.94,21.81 83.94,23.58 J2.27
  Bottom 0.254: U1.27 67.61,35.3 68.5,34.4 68.5,32.68 69.21,31.97 76.96,31.97 78.48,30.7 78.61,28.16 J2.27
P1.7  (via drill 0.3 pad 0.61)
  Top 0.254: v75.56,30.7 76.83,29.43 J2.28 82.93,29.43 84.2,29.43 | 84.2,29.43 | 84.2,29.43 S2.2
  Bottom 0.254: v75.56,30.7 67.3,30.7 66.44,31.56 66.44,34.73 65.4,35.78 65.42,35.8 U1.28
P8.0
  Top 0.254: U1.15 60.29,22.57 71.75,22.57 73.02,21.3 73.02,8.34 74.29,7.07 | 74.29,7.07 65.91,7.07 J1.15 | 74.29,7.07 LED.1
P8.1
  Top 0.254: J1.16 67.18,5.8 78.86,5.8 LED.3 81.4,5.8 81.4,7.84 80.89,8.34 79.37,8.34 78.61,7.58 74.54,7.58 73.53,8.6 73.53,23.33 71.75,25.11 60.25,25.11 U1.16
P8.2  (via drill 0.3)
  Top 0.254: LED.5 69.97,1.99 J1.17 | U1.17 60.72,27.14 72.26,27.14 74.04,25.36 74.04,11.9 74.8,11.14 v74.8,10.63
  Bottom 0.254: v74.8,10.63 74.8,7.84 76.83,5.8 76.83,2.76 77.59,1.99 LED.5
PU.0/DP  (via drill 0.3 pad 0.3)
  Top 0.254: U1.62 43.43,45.43 R34.1 40.85,47.88 v40.76,47.97 | v30.35,57.37 30.86,56.86 30.86,55.84 34.41,52.29 C35.1 35.68,52.29 35.68,50.42 R33.2 36.44,49.75 36.44,49.49 36.44,48.98 36.95,48.48 v38.98,48.48 39.07,48.39 R11.2
  Bottom 0.254: v40.76,47.97 39.24,47.97 v38.98,48.48 | J4.62 v30.35,57.37
PU.1/DM  (via drill 0.3 pad 0.3)
  Top 0.254: U1.64 45.56,40.38 42.03,43.9 41.02,43.9 | J4.64 28.57,48.48 C36.1 32.04,47.55 v36.95,42.63 | 41.02,43.9 R35.1 | v40.76,42.63 40.76,43.65 41.02,43.9
  Bottom 0.254: v36.95,42.63 v40.76,42.63
PUR  (via drill 0.3 pad 0.3)
  Top 0.254: U1.63 43.56,40.85 43.56,40.86 41.52,40.86 40,42.38 40,48.48 38.73,49.75 R33.1 38.06,50.42 v37.46,51.02 | v32.63,52.79 v30.6,54.83 29.84,54.83 29.33,55.33 29.33,61.43 25.78,64.99 R10.2
  Bottom 0.254: v37.46,51.02 34.41,51.02 v32.63,52.79 | J4.63 v30.6,54.83
RST  (via drill 0.3)
  Top 0.254: JP6.2 15.87,20.54 15.23,20.54 14.6,19.9 14.6,19.27 R5.1 | J4.76 26.54,23.58 26.54,26.63 27.55,27.65 31.62,27.65 32.63,28.66 32.63,29.93 34.16,31.46 34.16,32.22 34.41,32.47 35.43,32.47 35.68,32.22 39.49,32.22 39.57,32.3 C8.2 42.97,32.3 v43.05,32.22 | v44.32,30.95 45.84,30.95 46.6,31.71 46.6,33.24 45.56,34.28 U1.76
  Bottom 0.254: JP6.2 18.41,23.08 23.49,23.08 J4.76 | v43.05,32.22 v44.32,30.95
RST/NMI
  Bottom 0.254: JTAG.11 5.71,20.54 18.41,20.54 JP6.3
TCK
  Top 0.254: JP7.3 18.41,23.08 6.22,23.08 4.95,24.35 JTAG.7 2.66,26.12 2.66,32.47 3.93,35.01 12.31,35.01 13.08,35.78 13.08,37.48 R7.2
TDI
  Top 0.254: JTAG.3 4.95,29.43 6.22,28.16 17.65,28.16 18.92,29.43 JP9.3
TDO  (via drill 0.6)
  Top 0.254: JTAG.1 5.71,30.7 v12.31,30.7 18.41,30.7 JP10.3
  Bottom 0.254: JP6.1 14.09,21.68 12.31,23.2 12.31,25.06 v12.31,30.7
TEST/SBWTCK  (via drill 0.3)
  Top 0.254: JP5.2 JP5.3 | U1.71 49.4,34.96 49.4,31.97 48.38,30.95 | 48.38,30.95 48.26,30.82 | J4.71 25.27,34.51 26.28,33.49 26.28,32.73 v29.59,29.43 | v34.41,29.43 34.92,29.93 43.3,29.93 43.56,29.68 47.11,29.68 48.38,30.95
  Bottom 0.254: JP5.3 J4.71 | JTAG.8 11.04,29.68 11.04,32.47 11.81,33.24 15.87,33.24 JP5.2 | v29.59,29.43 29.84,29.43 30.09,29.68 34.16,29.68 v34.41,29.43
TMS
  Top 0.254: JTAG.5 4.95,26.89 6.22,25.62 17.65,25.62 18.92,26.89 JP8.3
V18  (via drill 0.3)
  Top 0.254: C38.1 34.41,43.9 v35.68,42.63
  Bottom 0.254: U1.67 45.81,38.8 46.6,39.59 46.6,45.43 45.84,46.19 43.05,46.19 42.54,45.68 42.54,42.63 41.78,41.87 40.76,41.62 36.44,41.62 36.19,41.87 v35.68,42.63 26.79,42.63 J4.67
VBUS  (via drill 0.3 pad 0.3)
  Top 0.254: IC7.6 16.41,57.66 v16.38,57.62
  Top 0.406: 17.14,61.68 C39.1 v17.14,60.16 | v17.39,55.59 C40.1 18.92,55.59 19.43,55.08 19.43,51.27 | D2.2 17.65,51.27 19.43,51.27 | J4.65 21.2,49.75 19.43,51.27 | U1.65 48.08,39.8 50.16,41.87 50.16,42.89 v49.14,43.9
  Bottom 0.406: v17.39,55.59 17.39,56.6 v16.38,57.62 17.14,58.38 v17.14,60.16 | v49.14,43.9 46.1,46.95 33.14,46.95 32.13,45.94 23.49,45.94 22.73,46.7 22.73,47.71 J4.65
VCC
  Top 0.406: JP1.1 5.71,50.76 5.71,69.56 J5.1 11.3,74.13 12.06,73.37 12.06,72.35 JP4.1
  Bottom 0.61: JP3.2 10.03,42.38 JP1.1
VUSB  (via drill 0.3 pad 0.3, 0.6)
  Top 0.406: U1.66 41.56,39.3 39.24,41.62 30.35,41.62 J4.66 | 35.68,53.81 C33.1 34.16,53.81 v33.4,54.57 | v25.52,70.83 D4.1
  Bottom 0.406: S3.1 19.43,70.58 20.95,72.1 24.25,72.1 v25.52,70.83 25.52,67.27 27.55,65.24 32.13,65.24 33.4,63.97 v33.4,54.57 32.13,54.57 J4.66
XIN  (via drill 0.8)
  Top 0.254: C2.1 51.68,15.2 51.61,15.13 R6.1 49.91,17.74 v50.16,18 Q1.2 52.19,18 52.19,21.81 52.95,22.57 56,22.57 57.26,23.83 U1.12
XOUT  (via drill 0.8)
  Top 0.254: 55.49,15.2 55.49,17.74 v55.24,18 Q1.1 | 55.49,15.2 R8.1 | C1.1 55.42,15.13 55.49,15.2
  Bottom 0.254: 57.78,26.12 | 57.78,26.12 U1.13 | 57.78,26.12 57.78,25.62 58.29,25.11 61.84,25.11 62.23,24.73 62.23,21.68 61.84,21.3 56,21.3 55.24,20.54 v55.24,18
XT2IN  (via drill 0.8)
  Top 0.254: v36.19,34 32.63,34 32.05,34.58 C4.1 32.13,34.76 32.05,34.68 R12.1
  Bottom 0.254: Q2.1 v36.19,34 36.19,31.97 36.7,31.46 40.76,31.46 41.02,31.71 41.02,33.49 41.78,34.25 41.78,36.03 43.54,37.8 U1.69
XT2OUT  (via drill 0.3, 0.8)
  Top 0.254: Q2.2 32.76,37.17 32.13,36.54 | U1.70 45.08,37.3 44.57,36.79 44.57,32.22 43.3,30.95 35.68,30.95 v34.92,31.71 | C3.1 32.13,36.54 | R9.1 32.05,36.61 32.13,36.54
  Bottom 0.254: 36.19,37.3 v36.19,39.08 | Q2.2 36.19,37.3 | v34.92,31.71 34.92,36.03 36.19,37.3
XTLGND1  (via drill 0.8)
  Top 0.254: 53.72,13.17 53.64,13.25
  Top 0.406: C1.2 53.72,13.17 52.95,12.41 | 52.95,12.41 v52.95,11.65 | C2.2 51.86,13.25 52.7,12.41 52.95,12.41
  Bottom 0.406: 47.11,15.2 48.64,15.2
  pour Bottom: 48.13,15.2 48.13,19.27 48.64,19.77 56.76,19.77 57.27,19.27 57.27,10.63 56.76,10.12 48.64,10.12 48.13,10.63
XTLGND2  (via drill 0.8)
  Top 0.406: C3.2 29.08,36.54 v28.32,35.78 29.33,34.76 C4.2
  Bottom 0.406: 39.24,37.81 40.76,37.81
  pour Bottom: 30.86,31.97 27.3,31.97 26.79,32.47 26.79,40.6 27.3,41.11 39.49,41.11 40,40.6 40,32.73 39.49,32.22 37.97,32.22 37.46,32.73 37.46,39.84 36.95,40.35 34.41,40.35 33.9,39.84 33.9,32.47 33.4,31.97

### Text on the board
tNames: int | Vcc | ext | MSP-TS430PN80USB | Rev.: 1.2 RoHS | SBW | JTAG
